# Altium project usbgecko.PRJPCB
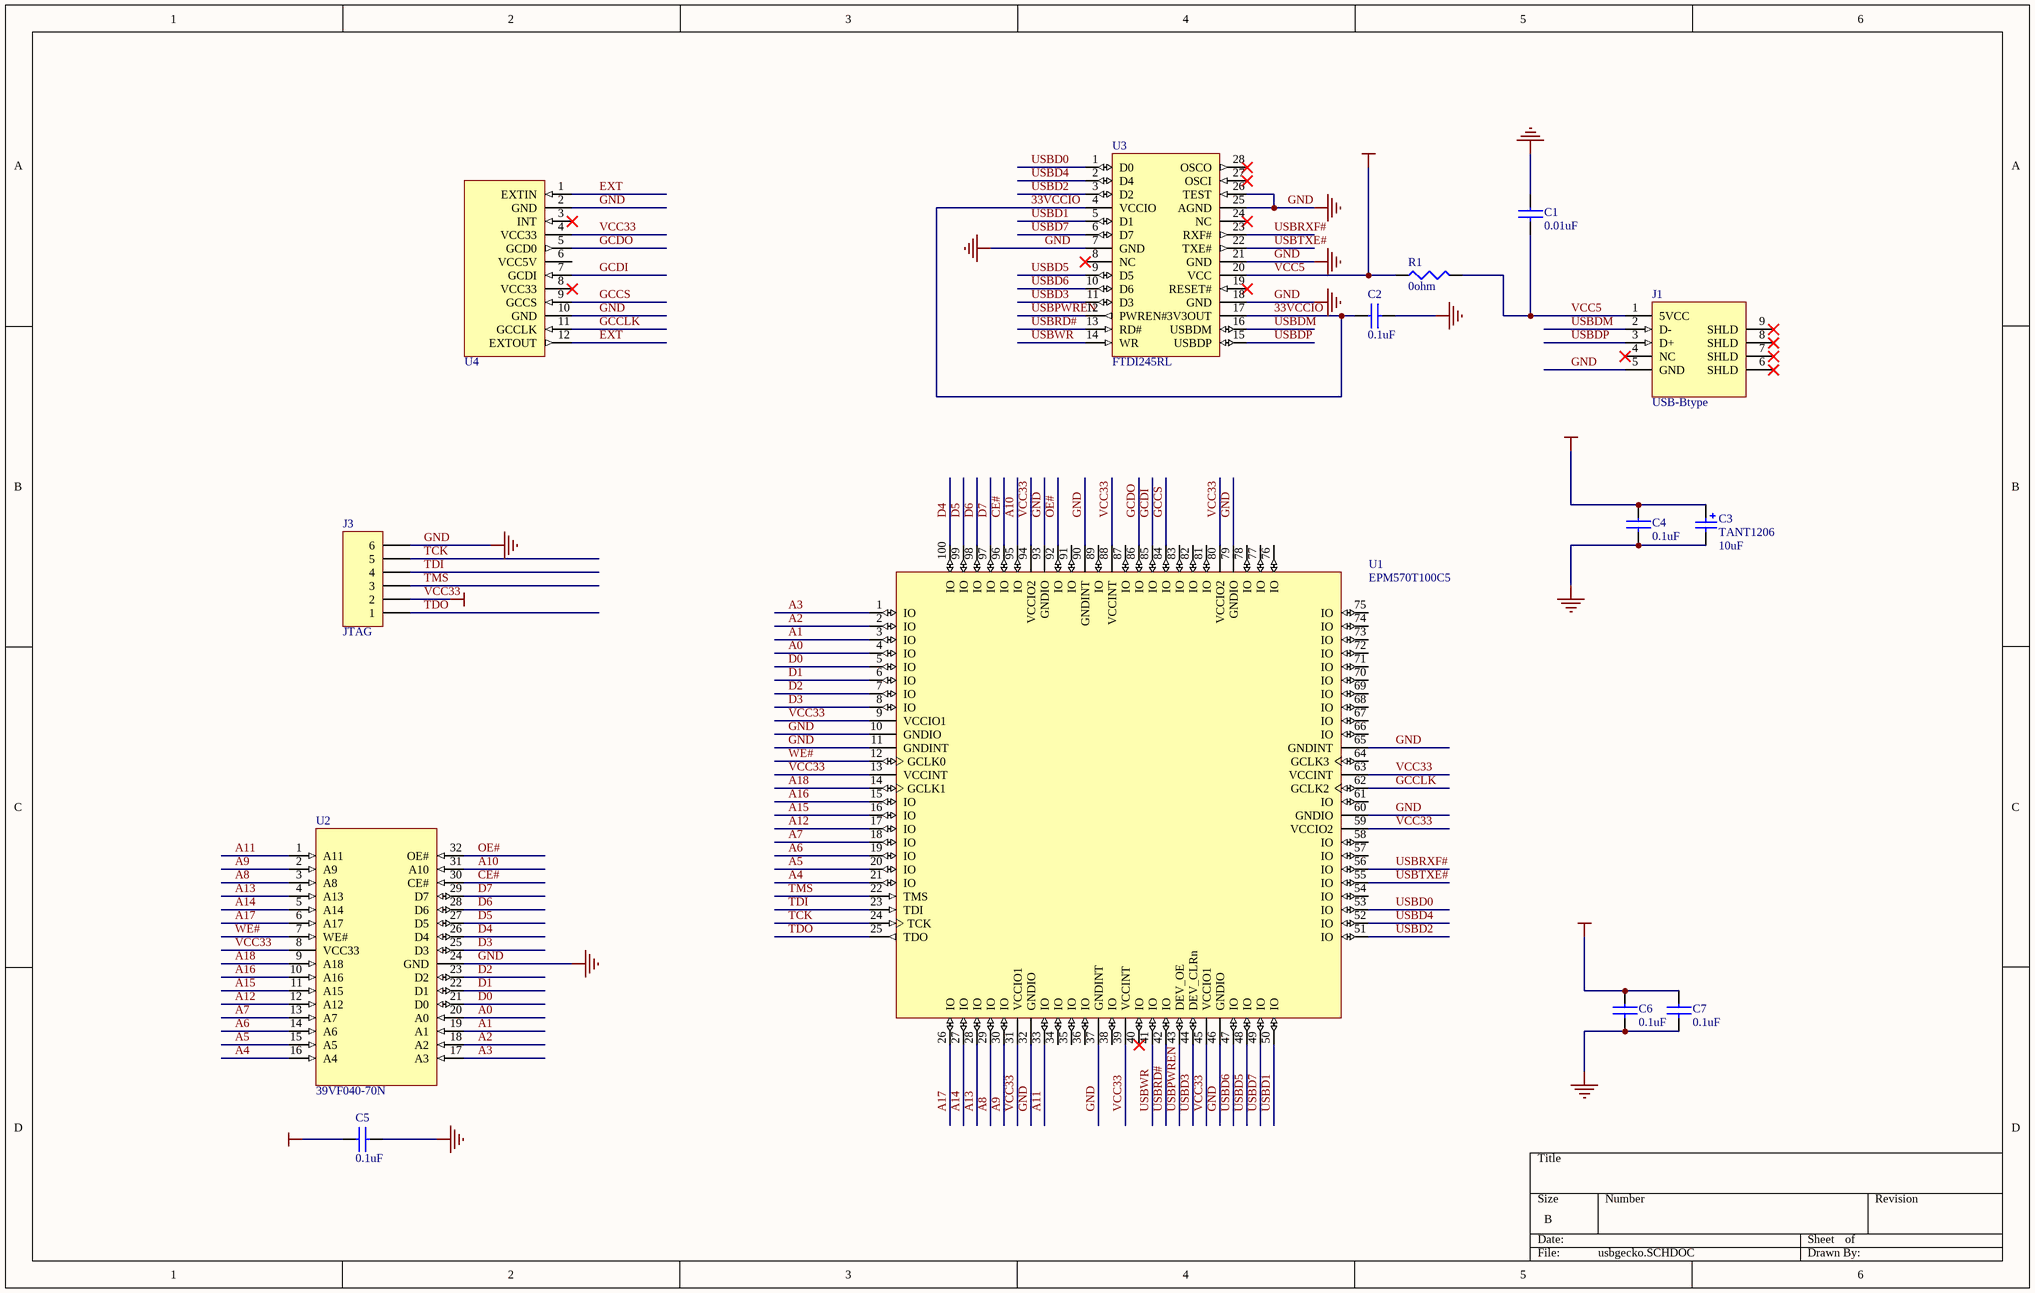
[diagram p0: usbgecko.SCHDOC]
1 sheet, 14 parts. Net scope: global (net labels, ports and power ports of the same name join across sheets).
Board file: usbgecko.PCBDOC

## Sheet usbgecko.SCHDOC
size B

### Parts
C1  0.01uF  [0603]
C2  0.1uF  [0603]
C3  TANT1206  value 10uF  [1206]
C4  0.1uF  [0603]
C5  0.1uF  [0603]
C6  0.1uF  [0603]
C7  0.1uF  [0603]
J1  USB-Btype  [Mini-USB-SMT]
J3  JTAG  [JTAG]
R1  0ohm  [RES805]
U1  EPM570T100C5  [F-QFP14X14-G100/X.3N]
U2  39VF040-70N  [TSSO8x14-32]
U3  FTDI245RL  [SSO-G28/X.4]
U4  GCMEMPADS  [GCMEMPADS]  (value not drawn)

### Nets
GND: C1.1 C2.2 C3.2 C4.2 C5.2 C6.2 C7.2 J1.5(GND) J3.6 U1.10(GNDIO) U1.11(GNDINT) U1.32(GNDIO) U1.37(GNDINT) U1.46(GNDIO) U1.60(GNDIO) U1.65(GNDINT) U1.79(GNDIO) U1.90(GNDINT) U1.93(GNDIO) U2.24(GND) U3.7(GND) U3.18(GND) U3.21(GND) U3.25(AGND) U3.26(TEST) U4.2(GND) U4.10(GND)
VCC5: C1.2 C3.1 C4.1 J1.1(5VCC) R1.1 R1.2 U3.20(VCC)
VCC33: C5.1 C6.1 C7.1 J3.2 U1.9(VCCIO1) U1.13(VCCINT) U1.31(VCCIO1) U1.39(VCCINT) U1.45(VCCIO1) U1.59(VCCIO2) U1.63(VCCINT) U1.80(VCCIO2) U1.88(VCCINT) U1.94(VCCIO2) U2.8(VCC33) U4.4(VCC33)
33VCCIO: C2.1 U3.4(VCCIO) U3.17(3V3OUT)
A0: U1.4(IO) U2.20(A0)
A1: U1.3(IO) U2.19(A1)
A2: U1.2(IO) U2.18(A2)
A3: U1.1(IO) U2.17(A3)
A4: U1.21(IO) U2.16(A4)
A5: U1.20(IO) U2.15(A5)
A6: U1.19(IO) U2.14(A6)
A7: U1.18(IO) U2.13(A7)
A8: U1.29(IO) U2.3(A8)
A9: U1.30(IO) U2.2(A9)
A10: U1.95(IO) U2.31(A10)
A11: U1.33(IO) U2.1(A11)
A12: U1.17(IO) U2.12(A12)
A13: U1.28(IO) U2.4(A13)
A14: U1.27(IO) U2.5(A14)
A15: U1.16(IO) U2.11(A15)
A16: U1.15(IO) U2.10(A16)
A17: U1.26(IO) U2.6(A17)
A18: U1.14(GCLK1) U2.9(A18)
CE#: U1.96(IO) U2.30(CE#)
D0: U1.5(IO) U2.21(D0)
D1: U1.6(IO) U2.22(D1)
D2: U1.7(IO) U2.23(D2)
D3: U1.8(IO) U2.25(D3)
D4: U1.100(IO) U2.26(D4)
D5: U1.99(IO) U2.27(D5)
D6: U1.98(IO) U2.28(D6)
D7: U1.97(IO) U2.29(D7)
EXT: U4.1(EXTIN) U4.12(EXTOUT)
GCCLK: U1.62(GCLK2) U4.11(GCCLK)
GCCS: U1.84(IO) U4.9(GCCS)
GCDI: U1.85(IO) U4.7(GCDI)
GCDO: U1.86(IO) U4.5(GCD0)
OE#: U1.92(IO) U2.32(OE#)
TCK: J3.5 U1.24(TCK)
TDI: J3.4 U1.23(TDI)
TDO: J3.1 U1.25(TDO)
TMS: J3.3 U1.22(TMS)
USBD0: U1.53(IO) U3.1(D0)
USBD1: U1.50(IO) U3.5(D1)
USBD2: U1.51(IO) U3.3(D2)
USBD3: U1.44(DEV_CLRn) U3.11(D3)
USBD4: U1.52(IO) U3.2(D4)
USBD5: U1.48(IO) U3.9(D5)
USBD6: U1.47(IO) U3.10(D6)
USBD7: U1.49(IO) U3.6(D7)
USBDM: J1.2(D-) U3.16(USBDM)
USBDP: J1.3(D+) U3.15(USBDP)
USBPWREN: U1.43(DEV_OE) U3.12(PWREN#)
USBRD#: U1.42(IO) U3.13(RD#)
USBRXF#: U1.56(IO) U3.23(RXF#)
USBTXE#: U1.55(IO) U3.22(TXE#)
USBWR: U1.41(IO) U3.14(WR)
WE#: U1.12(GCLK0) U2.7(WE#)

Not connected (* = marked no-connect by the designer): J1 4(NC)* 6(SHLD)* 7(SHLD)* 8(SHLD)* 9(SHLD)*; U1 34(IO) 35(IO) 36(IO) 38(IO) 40(IO)* 54(IO) 57(IO) 58(IO) 61(IO) 64(GCLK3) 66(IO) 67(IO) 68(IO) 69(IO) 70(IO) 71(IO) 72(IO) 73(IO) 74(IO) 75(IO) 76(IO) 77(IO) 78(IO) 81(IO) 82(IO) 83(IO) 87(IO) 89(IO) 91(IO); U3 8(NC)* 19(RESET#)* 24(NC)* 27(OSCI)* 28(OSCO)*; U4 3(INT)* 6(VCC5V) 8(VCC33)*

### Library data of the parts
C1 C2 C4-C7 = CAP603: Capacitor 603
C3 = TANT1206: Tant 1206 A106 J106; Package Information: Latest Revision: Mar-2001
J1 = USB-Btype: USB B Type Right Angle, SMT 5 Pin; ContactMaterial: Phosphor Bronze; ContactPlating: Gold (30) over Nickel; PCB_Layout: Complies with manufacturer's recommendation.; DrillSize: Corresponds to nominal value.; PanelGround: Without
J3 = JTAG: Altera Jtag; Manufacturer: Generic Components; Class I: Connector
R1 = RESISTOR805: Resistor 805 Package
U1 = EPM570T100C5: MAX II EPM 570 LE CPLD 100 Pin; Manufacturer: Altera; Class I: Programmable Logic Device; Class II: MAX II
U2 = 39VF040-70N: 4 Mbit (512Kb x8, Block Erase) Single Supply Flash Memory; Manufacturer: SST; Package Information: Latest Revision: Jul-1998; Class II: EEPROM
U3 = FTDI245RL: FTDI 245RL 28 pin SSOP; Manufacturer: SST; Package Information: Latest Revision: Jun-2006; Class I: Memory; Class II: Flash
U4 = GCMEMPADS: Gamecube Memory Card Pads; Manufacturer: DNS; Class I: Connector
